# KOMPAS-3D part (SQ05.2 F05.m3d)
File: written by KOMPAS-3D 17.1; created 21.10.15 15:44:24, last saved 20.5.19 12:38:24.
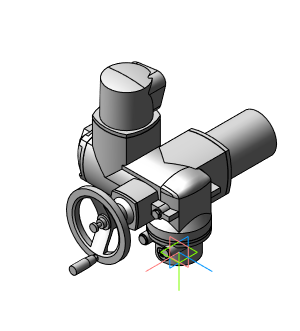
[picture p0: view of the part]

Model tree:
1. Операция без истории:3  (labels: Сталь 20  ГОСТ 1050-88)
